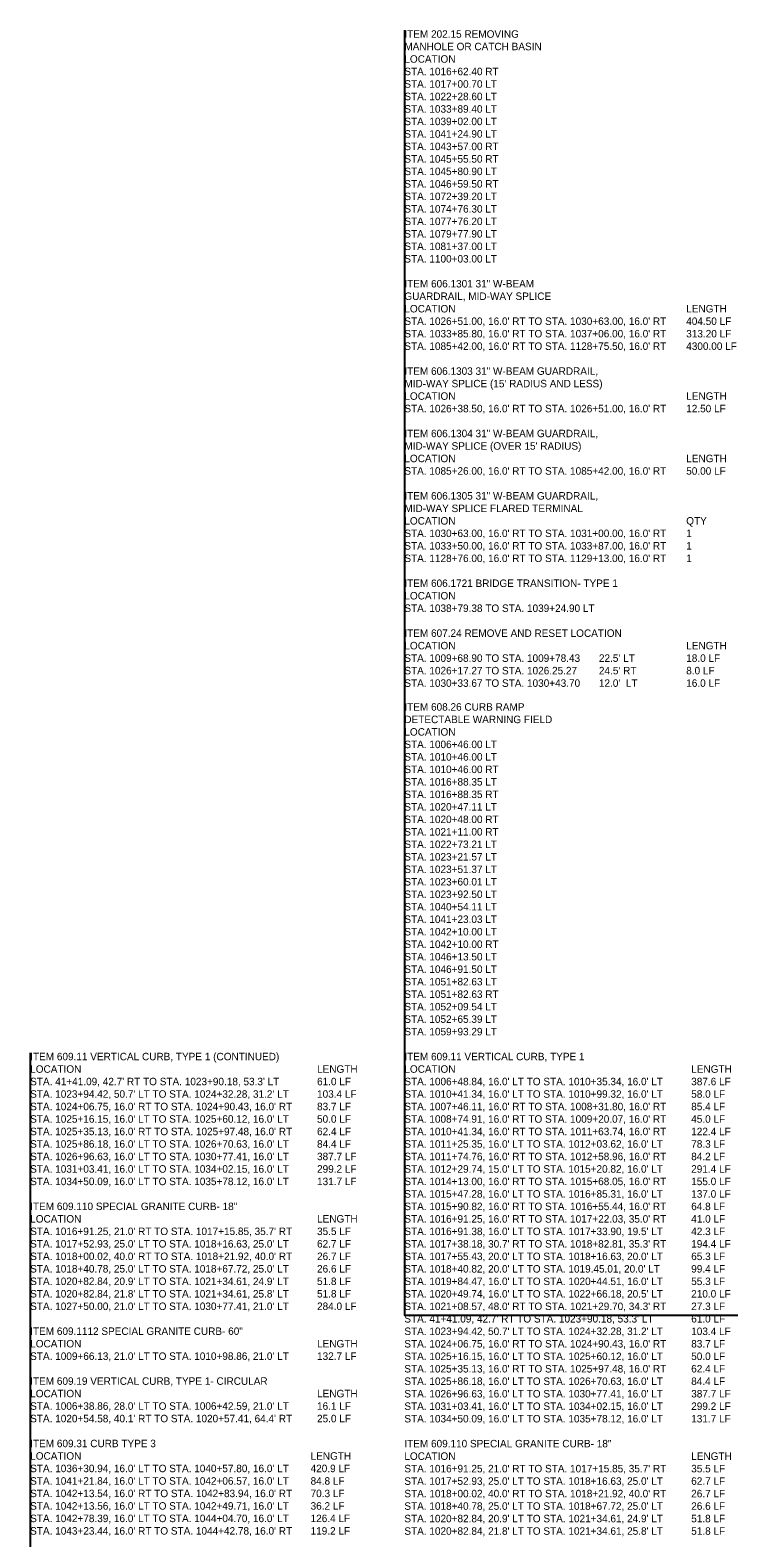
# Model space of a CAD drawing. Extents: x -831 to 3331, y -1004 to 250.
# Drawn here: x -307 to -23, y -399 to 206 of the extents above; entities that cross this region are included whole.
import ezdxf

# ---------------------------------------------------------------- set-up
doc = ezdxf.new("R2010")
doc.units = 0
doc.layers.add('Default', color=7, linetype='Continuous')

msp = doc.modelspace()

# ---------------------------------------------------------------- linework, layer by layer
at = {"layer": 'Default'}
for p, q in [((-156.76, 205.81), (-156.76, -305.19)), ((-306.76, -204.41), (-306.76, -715.41))]:
    msp.add_line(p, q, dxfattribs=at)
msp.add_lwpolyline([(-156.76, -305.19), (-156.76, -309.62), (-23.07, -309.62)], dxfattribs=at)

# ---------------------------------------------------------------- texts
for s, p in [('ITEM 202.15 REMOVING ', (-156.76, 202.81)), ('MANHOLE OR CATCH BASIN', (-156.76, 197.8)), ('LOCATION', (-156.76, 192.79)), ('STA. 1016+62.40 RT', (-156.76, 187.78)), ('STA. 1017+00.70 LT', (-156.76, 182.77)), ('STA. 1022+28.60 LT', (-156.76, 177.76)), ('STA. 1033+89.40 LT', (-156.76, 172.75)), ('STA. 1039+02.00 LT', (-156.76, 167.74)), ('STA. 1041+24.90 LT', (-156.76, 162.73)), ('STA. 1043+57.00 RT', (-156.76, 157.72)), ('STA. 1045+55.50 RT', (-156.76, 152.71)), ('STA. 1045+80.90 LT', (-156.76, 147.7)), ('STA. 1046+59.50 RT', (-156.76, 142.69)), ('STA. 1072+39.20 LT', (-156.76, 137.68)), ('STA. 1074+76.30 LT', (-156.76, 132.67)), ('STA. 1077+76.20 LT', (-156.76, 127.66)), ('STA. 1079+77.90 LT', (-156.76, 122.65)), ('STA. 1081+37.00 LT', (-156.76, 117.64)), ('STA. 1100+03.00 LT', (-156.76, 112.63)), ('ITEM 606.1301 31" W-BEAM ', (-156.76, 102.63)), ('GUARDRAIL, MID-WAY SPLICE', (-156.76, 97.62)), ('LOCATION', (-156.76, 92.61)), ('LENGTH', (-43.76, 92.61)), ("STA. 1026+51.00, 16.0' RT TO STA. 1030+63.00, 16.0' RT", (-156.76, 87.6)), ("STA. 1033+85.80, 16.0' RT TO STA. 1037+06.00, 16.0' RT", (-156.76, 82.59)), ('404.50 LF', (-43.76, 87.6)), ('313.20 LF', (-43.76, 82.59)), ("STA. 1085+42.00, 16.0' RT TO STA. 1128+75.50, 16.0' RT", (-156.76, 77.58)), ('4300.00 LF', (-43.76, 77.58)), ('ITEM 606.1303 31" W-BEAM GUARDRAIL, ', (-156.76, 67.58)), ("MID-WAY SPLICE (15' RADIUS AND LESS)", (-156.76, 62.57)), ('LOCATION', (-156.76, 57.56)), ('LENGTH', (-43.76, 57.56)), ("STA. 1026+38.50, 16.0' RT TO STA. 1026+51.00, 16.0' RT", (-156.76, 52.55)), ('12.50 LF', (-43.76, 52.55)), ('ITEM 606.1304 31" W-BEAM GUARDRAIL, ', (-156.76, 42.55)), ("MID-WAY SPLICE (OVER 15' RADIUS)", (-156.76, 37.54)), ("STA. 1085+26.00, 16.0' RT TO STA. 1085+42.00, 16.0' RT", (-156.76, 27.52)), ('LOCATION', (-156.76, 32.53)), ('50.00 LF', (-43.76, 27.52)), ('LENGTH', (-43.76, 32.53)), ('ITEM 606.1305 31" W-BEAM GUARDRAIL, ', (-156.76, 17.52)), ('MID-WAY SPLICE FLARED TERMINAL', (-156.76, 12.51)), ('LOCATION', (-156.76, 7.5)), ('QTY', (-43.76, 7.5)), ("STA. 1030+63.00, 16.0' RT TO STA. 1031+00.00, 16.0' RT", (-156.76, 2.49)), ("STA. 1033+50.00, 16.0' RT TO STA. 1033+87.00, 16.0' RT", (-156.76, -2.52)), ('1', (-43.76, 2.49)), ('1', (-43.76, -2.52)), ("STA. 1128+76.00, 16.0' RT TO STA. 1129+13.00, 16.0' RT", (-156.76, -7.53)), ('1', (-43.76, -7.53)), ('ITEM 606.1721 BRIDGE TRANSITION- TYPE 1', (-156.76, -17.53)), ('LOCATION', (-156.76, -22.54)), ('STA. 1038+79.38 TO STA. 1039+24.90 LT', (-156.76, -27.55)), ('ITEM 607.24 REMOVE AND RESET LOCATION', (-156.76, -37.55)), ('LOCATION', (-156.76, -42.56)), ('LENGTH', (-43.76, -42.56)), ('STA. 1009+68.90 TO STA. 1009+78.43', (-156.76, -47.57)), ("22.5' LT", (-78.76, -47.57)), ('18.0 LF', (-43.76, -47.57)), ('STA. 1026+17.27 TO STA. 1026.25.27', (-156.76, -52.58)), ("24.5' RT", (-78.76, -52.58)), ('8.0 LF', (-43.76, -52.58)), ('STA. 1030+33.67 TO STA. 1030+43.70', (-156.76, -57.59)), ("12.0'  LT", (-78.76, -57.59)), ('16.0 LF', (-43.76, -57.59)), ('ITEM 608.26 CURB RAMP ', (-156.76, -67.15)), ('DETECTABLE WARNING FIELD', (-156.76, -72.16)), ('LOCATION', (-156.76, -77.17)), ('STA. 1006+46.00 LT', (-156.76, -82.18)), ('STA. 1010+46.00 LT', (-156.76, -87.19)), ('STA. 1010+46.00 RT', (-156.76, -92.2)), ('STA. 1016+88.35 LT', (-156.76, -97.21)), ('STA. 1016+88.35 RT', (-156.76, -102.22)), ('STA. 1020+47.11 LT', (-156.76, -107.23)), ('STA. 1020+48.00 RT', (-156.76, -112.24)), ('STA. 1021+11.00 RT', (-156.76, -117.25)), ('STA. 1022+73.21 LT', (-156.76, -122.26)), ('STA. 1023+21.57 LT', (-156.76, -127.27)), ('STA. 1023+51.37 LT', (-156.76, -132.28)), ('STA. 1023+60.01 LT', (-156.76, -137.29)), ('STA. 1023+92.50 LT', (-156.76, -142.3)), ('STA. 1040+54.11 LT', (-156.76, -147.31)), ('STA. 1041+23.03 LT', (-156.76, -152.32)), ('STA. 1042+10.00 LT', (-156.76, -157.33)), ('STA. 1042+10.00 RT', (-156.76, -162.34)), ('STA. 1046+13.50 LT', (-156.76, -167.35)), ('STA. 1046+91.50 LT', (-156.76, -172.36)), ('STA. 1051+82.63 LT', (-156.76, -177.37)), ('STA. 1051+82.63 RT', (-156.76, -182.38)), ('STA. 1052+09.54 LT', (-156.76, -187.39)), ('STA. 1052+65.39 LT', (-156.76, -192.4)), ('STA. 1059+93.29 LT', (-156.76, -197.41)), ('ITEM 609.11 VERTICAL CURB, TYPE 1 (CONTINUED)', (-306.76, -207.41)), ('ITEM 609.11 VERTICAL CURB, TYPE 1', (-156.76, -207.41)), ('LOCATION', (-306.76, -212.42)), ('LENGTH', (-191.76, -212.42)), ('LOCATION', (-156.76, -212.42)), ('LENGTH', (-41.76, -212.42)), ("STA. 41+41.09, 42.7' RT TO STA. 1023+90.18, 53.3' LT", (-306.76, -217.43)), ('61.0 LF', (-191.76, -217.43)), ("STA. 1006+48.84, 16.0' LT TO STA. 1010+35.34, 16.0' LT", (-156.76, -217.43)), ('387.6 LF', (-41.76, -217.43)), ("STA. 1023+94.42, 50.7' LT TO STA. 1024+32.28, 31.2' LT", (-306.76, -222.44)), ('103.4 LF', (-191.76, -222.44)), ("STA. 1010+41.34, 16.0' LT TO STA. 1010+99.32, 16.0' LT", (-156.76, -222.44)), ('58.0 LF', (-41.76, -222.44)), ("STA. 1024+06.75, 16.0' RT TO STA. 1024+90.43, 16.0' RT", (-306.76, -227.45)), ("STA. 1025+16.15, 16.0' LT TO STA. 1025+60.12, 16.0' LT", (-306.76, -232.46)), ('50.0 LF', (-191.76, -232.46)), ('83.7 LF', (-191.76, -227.45)), ("STA. 1007+46.11, 16.0' RT TO STA. 1008+31.80, 16.0' RT", (-156.76, -227.45)), ("STA. 1008+74.91, 16.0' RT TO STA. 1009+20.07, 16.0' RT", (-156.76, -232.46)), ('45.0 LF', (-41.76, -232.46)), ('85.4 LF', (-41.76, -227.45)), ("STA. 1025+35.13, 16.0' RT TO STA. 1025+97.48, 16.0' RT", (-306.76, -237.47)), ('62.4 LF', (-191.76, -237.47)), ("STA. 1010+41.34, 16.0' RT TO STA. 1011+63.74, 16.0' RT", (-156.76, -237.47)), ('122.4 LF', (-41.76, -237.47)), ("STA. 1025+86.18, 16.0' LT TO STA. 1026+70.63, 16.0' LT", (-306.76, -242.48)), ('84.4 LF', (-191.76, -242.48)), ("STA. 1011+25.35, 16.0' LT TO STA. 1012+03.62, 16.0' LT ", (-156.76, -242.48)), ('78.3 LF', (-41.76, -242.48)), ("STA. 1026+96.63, 16.0' LT TO STA. 1030+77.41, 16.0' LT", (-306.76, -247.49)), ('387.7 LF', (-191.76, -247.49)), ("STA. 1011+74.76, 16.0' RT TO STA. 1012+58.96, 16.0' RT", (-156.76, -247.49)), ('84.2 LF', (-41.76, -247.49)), ("STA. 1031+03.41, 16.0' LT TO STA. 1034+02.15, 16.0' LT", (-306.76, -252.5)), ('299.2 LF', (-191.76, -252.5)), ("STA. 1012+29.74, 15.0' LT TO STA. 1015+20.82, 16.0' LT", (-156.76, -252.5)), ('291.4 LF', (-41.76, -252.5)), ("STA. 1034+50.09, 16.0' LT TO STA. 1035+78.12, 16.0' LT", (-306.76, -257.51)), ('131.7 LF', (-191.76, -257.51)), ("STA. 1014+13.00, 16.0' RT TO STA. 1015+68.05, 16.0' RT", (-156.76, -257.51)), ("STA. 1015+47.28, 16.0' LT TO STA. 1016+85.31, 16.0' LT", (-156.76, -262.52)), ('155.0 LF', (-41.76, -257.51)), ('137.0 LF', (-41.76, -262.52)), ('ITEM 609.110 SPECIAL GRANITE CURB- 18"', (-306.76, -267.51)), ("STA. 1015+90.82, 16.0' RT TO STA. 1016+55.44, 16.0' RT", (-156.76, -267.53)), ('64.8 LF', (-41.76, -267.53)), ('LOCATION', (-306.76, -272.52)), ('LENGTH', (-191.76, -272.52)), ("STA. 1016+91.25, 16.0' RT TO STA. 1017+22.03, 35.0' RT", (-156.76, -272.54)), ('41.0 LF', (-41.76, -272.54)), ("STA. 1016+91.25, 21.0' RT TO STA. 1017+15.85, 35.7' RT", (-306.76, -277.53)), ('35.5 LF', (-191.76, -277.53)), ("STA. 1016+91.38, 16.0' LT TO STA. 1017+33.90, 19.5' LT", (-156.76, -277.55)), ('42.3 LF', (-41.76, -277.55)), ("STA. 1017+52.93, 25.0' LT TO STA. 1018+16.63, 25.0' LT", (-306.76, -282.54)), ('62.7 LF', (-191.76, -282.54)), ("STA. 1017+38.18, 30.7' RT TO STA. 1018+82.81, 35.3' RT", (-156.76, -282.56)), ('194.4 LF', (-41.76, -282.56)), ("STA. 1018+00.02, 40.0' RT TO STA. 1018+21.92, 40.0' RT", (-306.76, -287.55)), ("STA. 1018+40.78, 25.0' LT TO STA. 1018+67.72, 25.0' LT ", (-306.76, -292.56)), ('26.7 LF', (-191.76, -287.55)), ('26.6 LF', (-191.76, -292.56)), ("STA. 1017+55.43, 20.0' LT TO STA. 1018+16.63, 20.0' LT", (-156.76, -287.57)), ("STA. 1018+40.82, 20.0' LT TO STA. 1019.45.01, 20.0' LT", (-156.76, -292.58)), ('99.4 LF', (-41.76, -292.58)), ('65.3 LF', (-41.76, -287.57)), ("STA. 1020+82.84, 20.9' LT TO STA. 1021+34.61, 24.9' LT", (-306.76, -297.57)), ('51.8 LF', (-191.76, -297.57)), ("STA. 1019+84.47, 16.0' LT TO STA. 1020+44.51, 16.0' LT", (-156.76, -297.59)), ('55.3 LF', (-41.76, -297.59)), ("STA. 1020+82.84, 21.8' LT TO STA. 1021+34.61, 25.8' LT", (-306.76, -302.58)), ('51.8 LF', (-191.76, -302.58)), ("STA. 1020+49.74, 16.0' LT TO STA. 1022+66.18, 20.5' LT", (-156.76, -302.6)), ('210.0 LF', (-41.76, -302.6)), ("STA. 1027+50.00, 21.0' LT TO STA. 1030+77.41, 21.0' LT", (-306.76, -307.59)), ('284.0 LF', (-191.76, -307.59)), ("STA. 1021+08.57, 48.0' RT TO STA. 1021+29.70, 34.3' RT", (-156.76, -307.61)), ('27.3 LF', (-41.76, -307.61)), ("STA. 41+41.09, 42.7' RT TO STA. 1023+90.18, 53.3' LT", (-156.76, -312.62)), ('61.0 LF', (-41.76, -312.62)), ('LOCATION', (-306.76, -322.6)), ('ITEM 609.1112 SPECIAL GRANITE CURB- 60"', (-306.76, -317.59)), ('LENGTH', (-191.76, -322.6)), ("STA. 1023+94.42, 50.7' LT TO STA. 1024+32.28, 31.2' LT", (-156.76, -317.63)), ("STA. 1024+06.75, 16.0' RT TO STA. 1024+90.43, 16.0' RT", (-156.76, -322.64)), ('83.7 LF', (-41.76, -322.64)), ('103.4 LF', (-41.76, -317.63)), ("STA. 1009+66.13, 21.0' LT TO STA. 1010+98.86, 21.0' LT", (-306.76, -327.61)), ('132.7 LF', (-191.76, -327.61)), ("STA. 1025+16.15, 16.0' LT TO STA. 1025+60.12, 16.0' LT", (-156.76, -327.65)), ('50.0 LF', (-41.76, -327.65)), ("STA. 1025+35.13, 16.0' RT TO STA. 1025+97.48, 16.0' RT", (-156.76, -332.66)), ('62.4 LF', (-41.76, -332.66)), ('ITEM 609.19 VERTICAL CURB, TYPE 1- CIRCULAR', (-306.76, -337.61)), ("STA. 1025+86.18, 16.0' LT TO STA. 1026+70.63, 16.0' LT", (-156.76, -337.67)), ('84.4 LF', (-41.76, -337.67)), ("STA. 1006+38.86, 28.0' LT TO STA. 1006+42.59, 21.0' LT", (-306.76, -347.63)), ('LOCATION', (-306.76, -342.62)), ('16.1 LF', (-191.76, -347.63)), ('LENGTH', (-191.76, -342.62)), ("STA. 1026+96.63, 16.0' LT TO STA. 1030+77.41, 16.0' LT", (-156.76, -342.68)), ("STA. 1031+03.41, 16.0' LT TO STA. 1034+02.15, 16.0' LT", (-156.76, -347.69)), ('387.7 LF', (-41.76, -342.68)), ('299.2 LF', (-41.76, -347.69)), ("STA. 1020+54.58, 40.1' RT TO STA. 1020+57.41, 64.4' RT", (-306.76, -352.64)), ('25.0 LF', (-191.76, -352.64)), ("STA. 1034+50.09, 16.0' LT TO STA. 1035+78.12, 16.0' LT", (-156.76, -352.7)), ('131.7 LF', (-41.76, -352.7)), ('ITEM 609.31 CURB TYPE 3', (-306.76, -362.64)), ('ITEM 609.110 SPECIAL GRANITE CURB- 18"', (-156.76, -362.7)), ('LOCATION', (-306.76, -367.65)), ('LENGTH', (-194.34, -367.65)), ('LOCATION', (-156.76, -367.71)), ('LENGTH', (-41.76, -367.71)), ("STA. 1036+30.94, 16.0' LT TO STA. 1040+57.80, 16.0' LT", (-306.76, -372.66)), ("STA. 1041+21.84, 16.0' LT TO STA. 1042+06.57, 16.0' LT", (-306.76, -377.67)), ('420.9 LF', (-194.34, -372.66)), ('84.8 LF', (-194.34, -377.67)), ("STA. 1016+91.25, 21.0' RT TO STA. 1017+15.85, 35.7' RT", (-156.76, -372.72)), ("STA. 1017+52.93, 25.0' LT TO STA. 1018+16.63, 25.0' LT", (-156.76, -377.73)), ('35.5 LF', (-41.76, -372.72)), ('62.7 LF', (-41.76, -377.73)), ("STA. 1042+13.54, 16.0' RT TO STA. 1042+83.94, 16.0' RT", (-306.76, -382.68)), ('70.3 LF', (-194.34, -382.68)), ("STA. 1018+00.02, 40.0' RT TO STA. 1018+21.92, 40.0' RT", (-156.76, -382.74)), ('26.7 LF', (-41.76, -382.74)), ("STA. 1042+13.56, 16.0' LT TO STA. 1042+49.71, 16.0' LT", (-306.76, -387.69)), ('36.2 LF', (-194.34, -387.69)), ("STA. 1018+40.78, 25.0' LT TO STA. 1018+67.72, 25.0' LT ", (-156.76, -387.75)), ('26.6 LF', (-41.76, -387.75)), ("STA. 1042+78.39, 16.0' LT TO STA. 1044+04.70, 16.0' LT", (-306.76, -392.7)), ('126.4 LF', (-194.34, -392.7)), ("STA. 1020+82.84, 20.9' LT TO STA. 1021+34.61, 24.9' LT", (-156.76, -392.76)), ('51.8 LF', (-41.76, -392.76)), ("STA. 1043+23.44, 16.0' RT TO STA. 1044+42.78, 16.0' RT", (-306.76, -397.71)), ('119.2 LF', (-194.34, -397.71)), ("STA. 1020+82.84, 21.8' LT TO STA. 1021+34.61, 25.8' LT", (-156.76, -397.77)), ('51.8 LF', (-41.76, -397.77))]:
    msp.add_text(s, height=3, dxfattribs=at).set_placement(p)

doc.saveas('drawing.dxf')
